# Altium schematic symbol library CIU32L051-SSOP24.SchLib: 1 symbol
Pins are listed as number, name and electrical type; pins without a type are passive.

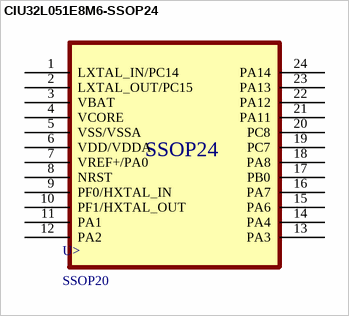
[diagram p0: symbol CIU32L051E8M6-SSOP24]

## CIU32L051E8M6-SSOP24
designator U>, comment SSOP20
footprint CIU32L051-SSOP-24N
pins: 1 LXTAL_IN/PC14, 2 LXTAL_OUT/PC15, 3 VBAT, 4 VCORE, 5 VSS/VSSA, 6 VDD/VDDA, 7 VREF+/PA0, 8 NRST, 9 PF0/HXTAL_IN, 10 PF1/HXTAL_OUT, 11 PA1, 12 PA2, 13 PA3, 14 PA4, 15 PA6, 16 PA7, 17 PB0, 18 PA8, 19 PC7, 20 PC8, 21 PA11, 22 PA12, 23 PA13, 24 PA14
